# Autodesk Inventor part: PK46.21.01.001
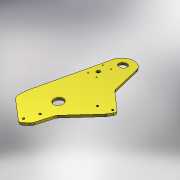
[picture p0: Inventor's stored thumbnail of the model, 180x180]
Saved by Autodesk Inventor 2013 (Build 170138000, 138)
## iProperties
Shininess: 64.0
Length Units: 11269
Angle Units: 11279
Time Units: 11290
Mass Units: 11283
Length Display Precision: 3
Angle Display Precision: 2
Compacted: True
Part Number: PK46.21.01.001
Document SubType Name: Modeling
Created: 2004-12
Designer: Salex
Manufacturer: Standard
Standards Organization: Custom
Material: Steel, Mild
Density: 7.86 g/cm^3
Density: 0.0
Volumn: 0.0
Area: 0.0
PropertySet Name: Model Information
Control State: 0
Master: False
Checked Out: False
Checked Out Date: 2008-10-15
Last Check In Date: 2008-10-15
Author: Salex
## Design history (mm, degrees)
sketch "Sketch1"
  geometry: L1 (-383.695, 252.148)-(-211.988, 855.987) reference; L2 (2.11, 845.209)-(57.62, 533.879); L3 (-106.182, 825.9)-(-105.034, 225.901); L4 (-56.182, 210.9)-(-513.806, 210.9) reference; L5 (-513.806, 170.9)-(-56.182, 170.9) reference; L6 (-330.034, 64.491)-(-130.034, 10.901); L7 (-130.034, 10.901)-(4.59, 160.901); L8 (-6.565, 872.552)-(243.818, 337.9) reference; L9 (53.882, 554.846)-(144.708, 360.901); L10 (144.708, 360.901)-(145.091, 160.901); L11 (145.091, 160.901)-(4.59, 160.901); L12 (-330.034, 64.491)-(-330.034, 170.9); L13 (-330.034, 164.491)-(-214.631, 844.31); C1 r 57.5 at (-106.182, 825.9) reference; C2 r 40 at (-106.182, 825.9) reference; C3 r 125 at (-105.034, 225.901); C4 r 40 at (-105.034, 225.901); A1 r 110 centre (-106.182, 825.9) between (-6.565, 872.552) and (-211.988, 855.987) reference; A2 r 110 centre (-106.182, 825.9) between (-6.565, 872.552) and (2.11, 845.209); 1 further point
  constraints: 18 end point, 4 point on line, 3 centre point, 3 coincident, 3 point on circle, 3 tangent, 1 equal radius, 1 horizontal, 1 parallel, 1 perpendicular
  dimensions: "d10" = 15 deg angle of L6 L5; "d11" = 10 deg angle of L2 L3; "d12" = 80 distance between parallel lines of L8 L9; "d13" = 250 distance between parallel lines of L10 L3; "d14" = 250 diameter of C3; "d15" = 200 distance of L9.end L10.end; "d17" = 600 distance of L3.start C3.centre; "d18" = 25 horizontal distance of L6.end C4.centre; "d19" = 200 distance from line of L6.end L12; "d20" = 65 distance from line of C4.centre L11; "d21" = 150 distance from line of L6.end L11; "d22" = 100 distance of L13.start L6.start
extrude "Extrusion1" new body sketch "Sketch1" distance "d6" = 20; taper "d7" = 0 deg
fillet "Fillet1" dims "d16" = 50
sketch "Эскиз2"
  geometry: L1 (-159.683, 18.846)-(-292.975, 54.561) reference; L2 (-10.311, 144.298)-(-109.531, 33.745) reference; L3 (94.995, 160.901)-(26.9, 160.901) reference; L4 (144.729, 349.823)-(144.995, 210.997) reference; L5 (56.671, 548.891)-(140.01, 370.933) reference; L6 (2.11, 845.209)-(52.728, 561.319) reference; L7 (-330.034, 164.491)-(-214.631, 844.31) reference; L8 (-330.034, 102.857)-(-330.034, 164.491) reference; L9 (-132.394, -13.523)-(-138.697, 26.1) reference; L10 (-77.322, 3.464)-(-107.844, -22.578) reference; L11 (-70.932, 77.506)-(-64.628, 37.883) reference; L12 (-126.003, 60.519)-(-95.481, 86.56) reference; L13 (-303.375, 58.64)-(-129.251, -33.276); L14 (-101.353, -30.185)-(-70.832, -4.143); L15 (-56.537, 17.162)-(-20.601, 126.511); C1 r 7 at (-117.58, -11.167) reference; C2 r 7 at (-85.745, 75.15) reference; A1 r 50 centre (-280.034, 102.857) between (-330.034, 102.857) and (-292.975, 54.561) reference; A2 r 50 centre (-146.742, 67.142) between (-159.683, 18.846) and (-109.531, 33.745) reference; A3 r 50 centre (26.9, 110.901) between (26.9, 160.901) and (-10.311, 144.298) reference; A4 r 50 centre (94.995, 210.901) between (94.995, 160.901) and (144.995, 210.997) reference; A5 r 50 centre (94.73, 349.727) between (144.729, 349.823) and (140.01, 370.933) reference; A6 r 50 centre (101.951, 570.096) between (52.728, 561.319) and (56.671, 548.891) reference; A7 r 110 centre (-106.182, 825.9) between (2.11, 845.209) and (-214.631, 844.31) reference; A8 r 15 centre (-117.58, -11.167) between (-132.394, -13.523) and (-107.844, -22.578) reference; A9 r 15 centre (-85.745, 75.15) between (-70.932, 77.506) and (-95.481, 86.56) reference; A10 r 37.5 centre (-101.663, 31.991) between (-126.003, 60.519) and (-138.697, 26.1) reference; A11 r 37.5 centre (-101.663, 31.991) between (-77.322, 3.464) and (-64.628, 37.883) reference; A12 r 25 centre (-117.58, -11.167) between (-129.251, -33.276) and (-101.353, -30.185); A13 r 47.5 centre (-101.663, 31.991) between (-70.832, -4.143) and (-56.537, 17.162); A14 r 50 centre (26.9, 110.901) between (26.9, 160.901) and (-20.601, 126.511)
  constraints: 15 end point, 15 point on circle, 9 centre point, 6 tangent, 3 concentric, 1 coincident, 1 parallel, 24 other
  dimensions: "d23" = 10 distance between parallel lines of L14 L10
extrude "Выдавливание2" join sketch "Эскиз2" distance "d24" = 20; taper "d25" = 0 deg
sketch "Эскиз3"
  geometry: L1 (94.995, 160.901)-(26.9, 160.901) reference; L2 (144.729, 349.823)-(144.995, 210.997) reference; L3 (-9.857, 144.797)-(167.611, 337.239); L4 (144.801, 312.505)-(144.995, 210.997); L5 (94.995, 160.901)-(26.9, 160.901); C1 r 26 at (132.692, 369.441) reference; A1 r 50 centre (26.9, 110.901) between (26.9, 160.901) and (-20.601, 126.511) reference; A2 r 50 centre (94.995, 210.901) between (94.995, 160.901) and (144.995, 210.997) reference; A3 r 37.5 centre (132.692, 369.441) between (132.764, 331.941) and (164.726, 349.945) reference; A4 r 50 centre (94.995, 210.901) between (94.995, 160.901) and (144.995, 210.997); A5 r 50 centre (26.9, 110.901) between (26.9, 160.901) and (-9.857, 144.797); 1 further point
  constraints: 7 point on circle, 6 end point, 4 centre point, 2 concentric, 2 point on line, 2 tangent, 1 coincident, 1 collinear, 10 other
  dimensions: "d26" = 10 dimension on A3
extrude "Выдавливание3" cut sketch "Эскиз3" stored distance "d27" = 20; taper "d28" = 0 deg
sketch "Эскиз4"
  geometry: L1 (-9.857, 144.797)-(144.801, 312.505) reference; L2 (144.729, 349.823)-(144.801, 312.505) reference; L3 (56.671, 548.891)-(140.01, 370.933) reference; L4 (2.11, 845.209)-(52.728, 561.319) reference; L5 (-330.034, 164.491)-(-214.631, 844.31) reference; L6 (-330.034, 102.857)-(-330.034, 164.491) reference; L7 (-303.375, 58.64)-(-129.251, -33.276) reference; L8 (-101.353, -30.185)-(-70.832, -4.143) reference; L9 (-56.537, 17.162)-(-20.601, 126.511) reference; L10 (66.427, 534.91)-(190.533, 409.61); L11 (144.801, 312.505)-(167.611, 337.239); L12 (194.127, 379.021)-(173.269, 344.747); A1 r 50 centre (94.73, 349.727) between (144.729, 349.823) and (140.01, 370.933) reference; A2 r 50 centre (101.951, 570.096) between (52.728, 561.319) and (56.671, 548.891) reference; A3 r 110 centre (-106.182, 825.9) between (2.11, 845.209) and (-214.631, 844.31) reference; A4 r 50 centre (-280.034, 102.857) between (-330.034, 102.857) and (-303.375, 58.64) reference; A5 r 25 centre (-117.58, -11.167) between (-129.251, -33.276) and (-101.353, -30.185) reference; A6 r 47.5 centre (-101.663, 31.991) between (-70.832, -4.143) and (-56.537, 17.162) reference; A7 r 50 centre (26.9, 110.901) between (-9.857, 144.797) and (-20.601, 126.511) reference; A8 r 47.5 centre (132.692, 369.441) between (167.611, 337.239) and (173.269, 344.747); A9 r 50 centre (101.951, 570.096) between (52.728, 561.319) and (66.427, 534.91); A10 r 25 centre (172.77, 392.017) between (194.127, 379.021) and (190.533, 409.61)
  constraints: 7 end point, 6 point on circle, 6 tangent, 3 centre point, 1 coincident, 1 concentric
extrude "Выдавливание4" join sketch "Эскиз4" distance "d30" = 20; taper "d31" = 0 deg
sketch "Эскиз6"
  geometry: C1 r 17.5 at (-170.819, 635.776) reference
  constraints: 1 centre point, 2 other
extrude "Выдавливание6" cut sketch "Эскиз6" stored distance "d36" = 10; taper "d37" = 0 deg
sketch "Sketch7"
  geometry: C1 r 5.5 at (-210.991, 725.699) reference; C2 r 5.5 at (-130.704, 575.853) reference; C3 r 5.5 at (-210.704, 575.699) reference; C4 r 5.5 at (-130.991, 725.852) reference; 1 further point
  constraints: 4 centre point, 8 other
  dimensions: "d39" = 11 diameter of C3 (derived)
hole "Hole1" sketch "Sketch7" at (-210.991, 725.699), (-130.991, 725.852), (-130.704, 575.853), (-210.704, 575.699) diameter "d40" = 9.376; stored, may be unused: countersink angle "d44" = 90 deg, drill point angle "d46" = 118 deg; dims "d41" = 12, "d42" = 4, "d43" = 2, "d45" = 8
sketch "Sketch8"
  geometry: C1 r 9 at (172.77, 392.017) reference; C2 r 9 at (87.755, 356.854) reference; C3 r 9 at (-88.174, 80.145) reference; C4 r 9 at (-120.009, -6.172) reference; 1 further point
  constraints: 4 centre point, 8 other
  dimensions: "d47" = 18 diameter of C1 (derived)
hole "Hole2" sketch "Sketch8" at (172.77, 392.017), (87.755, 356.854), (-88.174, 80.145), (-120.009, -6.172) diameter "d48" = 15.294; stored, may be unused: countersink angle "d52" = 90 deg, drill point angle "d54" = 118 deg; dims "d49" = 15, "d50" = 4, "d51" = 2, "d53" = 8
body "Solid1"
node "Reference1"
node "Reference2"
node "Reference5"
node "Reference6"
node "Reference7"
node "Reference8"
